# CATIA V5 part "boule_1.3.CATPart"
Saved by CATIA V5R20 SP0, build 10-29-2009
Part number: boule_1.3
Bounding box of the stored display mesh (mm): x 430.778 to 526.604, y 1210.969 to 1310.962, z -501.861 to -401.886
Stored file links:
  D:\thinkmotion-MPB\Dropbox\MMS_GR3\CFAO_2010_bfoltzer\CFAO_bfoltzer\boule_1.3.CATPart
  D:\ecole\thinkmotion\Eolienne.CATProduct
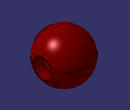
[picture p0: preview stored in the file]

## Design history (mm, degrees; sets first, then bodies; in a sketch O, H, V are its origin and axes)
External parameters (linked from other documents)
  External.rayon_barre = 20 mm
Set1
  Plane1: linked copy from another document
  Point1 to Point3: linked copy from another document
  Line1: linked copy from another document
  Point4: linked copy from another document
  Plane2: linked copy from another document
  Plane3: linked copy from another document
Body1 (main body)
  Sketch1 on Plane1, origin (0, 52.6643, 86.6621), H (1, 0, 0), V (0, -0.9134, 0.4071)
    arc A1 centre (480.7782, -1322.8803) radius 50 from (530.7782, -1322.8803) to (430.7782, -1322.8803) ccw
    point P1 (480.7782, -1322.8803)
    point P2 (530.7782, -1322.8803)
    point P3 (430.7782, -1322.8803)
    reference projected point E1 (530.7782, -1322.8803) from Point1
    reference projected point E2 (430.7782, -1322.8803) from Point2
    reference projected point E3 (480.7782, -1322.8803) from Point3
    coincidence: P2 E1, P3 E2, P1 E3
  Shaft1: profile Sketch1, axis Line1, angle 360
  Sketch2 on {plane type Tangent, Support face of Shaft1 from Sketch1.A1, RefPoint Point4}, origin (480.7782, 456.5148, -2133.9803), H (1, 0, 0), V (0, -0.4071, -0.9134)
    point P1 (0, -1863.9002)
    reference projected point E1 (0, -1863.9002) from Point4
    coincidence: E1 P1
  Hole1: placed by Sketch2, at (480.7782, 1215.2961, -431.5189) direction (0, 0.9134, -0.4071), diameter 40 {= External.rayon_barre *2}, up to Plane2
  Sketch3 on {plane type Tangent, Support face of Shaft1 from Sketch1.A1, RefPoint Point1}, origin (530.7782, 956.2569, -563.6246), H (0, 1, 0), V (0, 0, -1)
    point P1 (304.7085, -111.751)
    reference projected point E1 (304.7085, -111.751) from Point1
    coincidence: E1 P1
  Hole2: placed by Sketch3, at (530.7782, 1260.9654, -451.8736) direction (-1, 0, 0), diameter 40 {= External.rayon_barre *2}, up to Plane3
